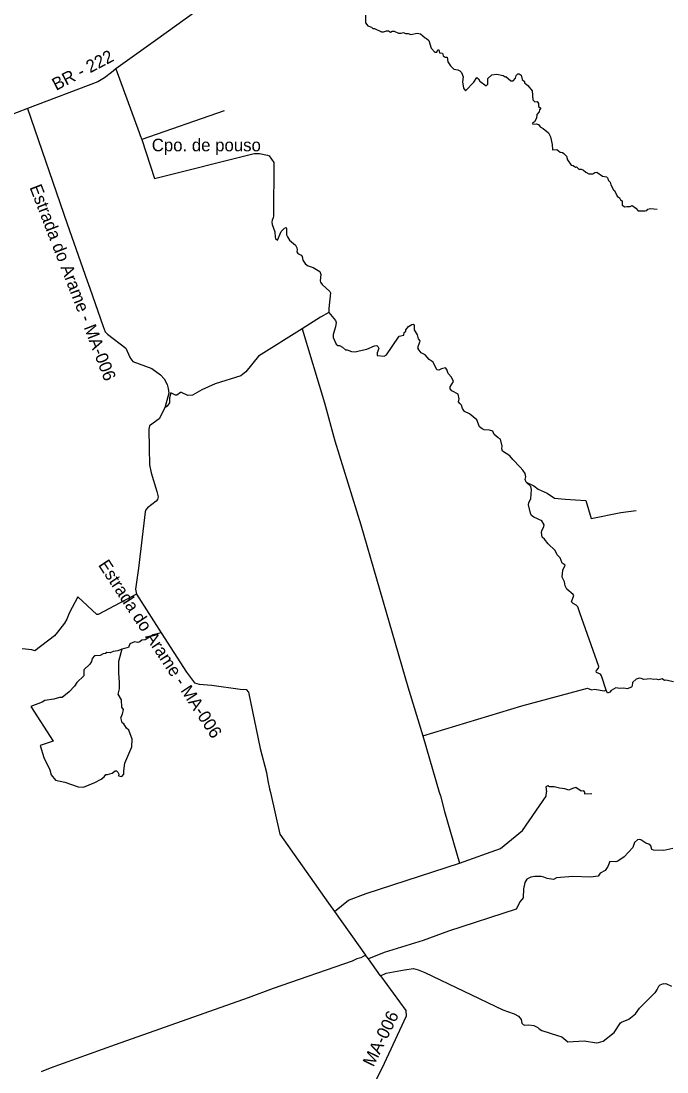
# Model space of a CAD drawing. Extents: x 332 to 501, y 9447 to 9559.
# Drawn here: x 359.78 to 379.35, y 9494.03 to 9525.86 of the extents above; entities that cross this region are included whole.
import ezdxf

# ---------------------------------------------------------------- set-up
doc = ezdxf.new("R2010")
doc.units = 0
for name, color, linetype in [('Level 1', 7, 'Continuous'), ('Level 13', 7, 'Continuous'), ('Level 2', 7, 'Continuous'), ('Level 31', 7, 'Continuous'), ('Level 5', 7, 'Continuous'), ('Level 6', 7, 'Continuous')]:
    doc.layers.add(name, color=color, linetype=linetype)

msp = doc.modelspace()

# ---------------------------------------------------------------- linework, layer by layer
at = {"layer": 'Level 1'}
msp.add_lwpolyline([(365.9301, 9523.1314), (363.4371, 9522.2704)], dxfattribs=at)
at = {"layer": 'Level 2'}
for points in [[(365.0749, 9526.1487), (363.8547, 9525.2686)], [(363.8547, 9525.2686), (362.6539, 9524.4042)], [(362.5174, 9524.3004), (362.304, 9524.1375), (362.1039, 9524.0174), (359.9733, 9523.2053)], [(362.6539, 9524.4042), (362.5174, 9524.3004)], [(359.9733, 9523.2053), (359.3502, 9522.9681), (356.5186, 9523.1911)], [(359.9733, 9523.2053), (361.1794, 9519.7092)], [(361.1794, 9519.7092), (361.7821, 9517.9924)], [(361.7821, 9517.9924), (361.8598, 9517.7681)], [(361.8598, 9517.7681), (362.2636, 9516.6001), (362.3311, 9516.447), (362.3941, 9516.375), (362.9521, 9515.9441), (363.0722, 9515.6726)], [(363.0722, 9515.6726), (363.0736, 9515.6676)], [(363.0736, 9515.6676), (363.1621, 9515.5469), (363.738, 9515.3308), (364.008, 9515.1372), (364.116, 9515.0201), (364.2015, 9514.8445), (364.2354, 9514.7302), (364.2534, 9514.5861), (364.1373, 9514.1464)], [(364.1373, 9514.1464), (363.9637, 9513.807), (363.672, 9513.5953), (363.6556, 9513.4916), (363.661, 9512.9157)], [(363.661, 9512.9157), (363.6725, 9512.4104), (363.7188, 9512.1731)], [(363.7188, 9512.1731), (363.896, 9511.6106), (363.9314, 9511.4469), (363.9124, 9511.3705), (363.8742, 9511.3187), (363.6097, 9511.1168), (363.5579, 9511.0568), (363.5416, 9510.9886), (363.3396, 9509.2835), (363.2469, 9508.6506), (363.2765, 9508.4962)], [(363.2765, 9508.4962), (364.0258, 9507.332)], [(364.0258, 9507.332), (364.79, 9506.1345), (365.0358, 9505.8141), (365.1787, 9505.7684), (365.5617, 9505.7398), (366.4193, 9505.6196), (366.5965, 9505.6139), (366.6651, 9505.5281), (367.0235, 9503.826), (367.2167, 9503.1019), (367.2567, 9502.8502)], [(367.2567, 9502.8502), (367.3073, 9502.6032)], [(367.3073, 9502.6032), (367.3315, 9502.4958)], [(367.3315, 9502.4958), (367.6153, 9501.2307), (369.0906, 9499.1393)], [(369.0906, 9499.1393), (369.2705, 9498.8886)], [(369.2705, 9498.8886), (370.2169, 9497.5702)], [(370.3034, 9497.4508), (370.2169, 9497.5702)], [(370.6661, 9496.9394), (370.3034, 9497.4508)], [(370.6661, 9496.9394), (371.4317, 9495.8895), (371.441, 9495.7173), (370.7059, 9494.1339), (369.2463, 9491.221), (368.7582, 9490.8961)]]:
    msp.add_lwpolyline(points, dxfattribs=at)
at = {"layer": 'Level 5'}
for points in [[(370.2183, 9526.0324), (370.2094, 9525.8015), (370.2849, 9525.7131), (370.3936, 9525.6665), (370.4353, 9525.6269), (370.4885, 9525.6269), (370.7032, 9525.5314), (370.7631, 9525.527), (370.8541, 9525.5581), (370.9074, 9525.5581), (370.9731, 9525.5226), (371.022, 9525.547), (371.0797, 9525.5448), (371.2106, 9525.4915), (371.2949, 9525.487), (371.3637, 9525.5048), (371.428, 9525.4826), (371.5101, 9525.4782), (371.5834, 9525.4493), (371.7808, 9525.4915), (371.8785, 9525.4715), (372.0177, 9525.3427), (372.065, 9525.3229)], [(372.065, 9525.3229), (372.1353, 9525.2693), (372.2075, 9525.0319), (372.3159, 9524.9132)], [(372.3159, 9524.9132), (372.3716, 9524.91), (372.4077, 9524.9823), (372.4335, 9524.9875), (372.4541, 9524.8894), (372.5419, 9524.879), (372.5625, 9524.8016), (372.6244, 9524.7655), (372.6863, 9524.7655), (372.7121, 9524.6157), (372.7895, 9524.497), (372.8927, 9524.3989), (373.0114, 9524.3782), (373.0682, 9524.3524), (373.1198, 9524.2956), (373.1714, 9524.1666), (373.1559, 9524.0117), (373.1869, 9523.8206), (373.2385, 9523.738), (373.4913, 9524.0013), (373.5893, 9524.1459), (373.6409, 9524.1098), (373.677, 9524.0323), (373.8731, 9523.8929), (373.9196, 9523.9394), (373.9196, 9524.1149), (374.0382, 9524.2234)], [(362.6539, 9524.4042), (363.3575, 9522.4841)], [(374.0382, 9524.2234), (374.1922, 9524.2459), (374.3852, 9524.2062), (374.442, 9524.1665), (374.4647, 9524.1721), (374.6123, 9524.0472), (374.6918, 9524.0472), (374.7599, 9524.121), (374.7826, 9524.2062), (374.828, 9524.2516), (374.8734, 9524.2573), (374.9302, 9524.2119), (374.9586, 9524.0813), (375.0324, 9524.0245), (375.0324, 9523.9791), (375.1289, 9523.9053), (375.2595, 9523.7407), (375.2878, 9523.4682), (375.3446, 9523.4115), (375.4184, 9523.4228), (375.4581, 9523.3604), (375.4581, 9523.2639), (375.5206, 9523.2128)], [(375.5206, 9523.2128), (375.4865, 9523.1674), (375.4752, 9523.1049), (375.4014, 9523.0254), (375.39, 9522.9176), (375.3332, 9522.804), (375.2765, 9522.7643)], [(375.2765, 9522.7643), (375.2822, 9522.7359), (375.3957, 9522.7416), (375.4581, 9522.7246), (375.5092, 9522.6565), (375.6001, 9522.6054), (375.7533, 9522.4748), (375.8214, 9522.3499), (375.8713, 9522.1197), (375.877, 9521.955)], [(363.3575, 9522.4841), (363.3928, 9522.3928)], [(363.3928, 9522.3928), (363.4371, 9522.2704)], [(363.4371, 9522.2704), (363.8235, 9521.0914)], [(375.877, 9521.955), (376.0076, 9521.9663), (376.1154, 9521.8811), (376.1835, 9521.8755), (376.2233, 9521.8471), (376.3027, 9521.7675), (376.3311, 9521.6539), (376.439, 9521.4892), (376.5071, 9521.4835), (376.5785, 9521.4298), (376.6069, 9521.4354), (376.6807, 9521.3673), (376.7488, 9521.3673), (376.8169, 9521.3389), (376.885, 9521.2764), (376.9758, 9521.231), (377.1007, 9521.2253), (377.1575, 9521.2707), (377.2199, 9521.2764), (377.3959, 9521.1571), (377.5151, 9521.1344), (377.5435, 9521.1117), (377.5719, 9521.0265), (377.623, 9520.9754), (377.6457, 9520.8958), (377.7252, 9520.7481), (377.7592, 9520.7197), (377.8387, 9520.555), (377.9068, 9520.4982), (377.9409, 9520.4357), (377.9863, 9520.413), (377.9863, 9520.3562)], [(363.8235, 9521.0914), (366.8443, 9521.8422), (367.0043, 9521.8472), (367.2496, 9521.7982), (367.2933, 9521.7736), (367.4323, 9521.5746), (367.4296, 9519.9548), (367.4187, 9519.892), (367.3832, 9519.8238), (367.3805, 9519.7638), (367.3859, 9519.6956), (367.465, 9519.4719), (367.4732, 9519.311), (367.4895, 9519.2701), (367.5441, 9519.2237), (367.6613, 9519.4774), (367.7567, 9519.5838), (367.8112, 9519.6002), (367.8249, 9519.562), (367.8249, 9519.3792), (367.8521, 9519.3219), (367.9094, 9519.221), (368.0967, 9519.0671), (368.1321, 9518.988), (368.143, 9518.9253), (368.1321, 9518.868), (368.1621, 9518.8162), (368.2603, 9518.7616), (368.293, 9518.7207), (368.3121, 9518.617), (368.3557, 9518.5516), (368.3993, 9518.497), (368.4756, 9518.4424), (368.6283, 9518.3961), (368.8293, 9518.2687), (368.862, 9518.1814), (368.8402, 9517.9877), (368.8538, 9517.9468), (368.9001, 9517.8813), (369.1319, 9517.6696), (369.1564, 9517.626), (369.0992, 9517.1541), (369.1046, 9517.0321)], [(377.9863, 9520.3562), (377.9863, 9520.2767), (378.0658, 9520.2256), (378.1282, 9520.2426), (378.2361, 9520.2369), (378.2928, 9520.2653), (378.4064, 9520.1858), (378.4745, 9520.1063), (378.6902, 9520.1063), (378.7356, 9520.1177), (378.7697, 9520.1574), (378.8491, 9520.1745), (379.0535, 9520.1631)], [(369.1046, 9517.0321), (369.3064, 9516.7866), (369.3254, 9516.7212), (369.3091, 9516.5989), (369.2382, 9516.3644)], [(368.2955, 9516.5359), (368.9764, 9514.2899), (369.29, 9513.1418), (370.0703, 9510.5959), (371.4932, 9505.6902), (371.9498, 9504.2075)], [(369.2382, 9516.3644), (369.2327, 9516.2689), (369.3227, 9516.0706), (369.3772, 9516.0324), (369.429, 9516.0269), (369.5179, 9515.9833), (369.6079, 9515.9014), (369.657, 9515.9014), (369.7933, 9515.8441), (369.8996, 9515.8332), (370.0187, 9515.872), (370.2532, 9515.9156), (370.4822, 9516.0165), (370.5558, 9516.0247), (370.5913, 9515.9974), (370.6131, 9515.9374), (370.5695, 9515.8065), (370.5695, 9515.7274), (370.7767, 9515.711), (370.8475, 9515.7438), (371.2115, 9516.2866), (371.2388, 9516.3139), (371.3723, 9516.3466), (371.3833, 9516.4202), (371.4378, 9516.4612), (371.4378, 9516.5075), (371.5196, 9516.603), (371.6177, 9516.6657), (371.6613, 9516.6767), (371.6859, 9516.6521), (371.6913, 9516.4993), (371.7813, 9516.3548), (371.814, 9516.2348), (371.8549, 9516.172), (371.8522, 9516.1256), (371.7922, 9515.9592)], [(371.7922, 9515.9592), (371.807, 9515.9303)], [(374.898, 9512.347), (374.675, 9512.574), (374.589, 9512.689), (374.366, 9512.829), (374.346, 9512.897), (374.355, 9512.981), (374.305, 9513.197), (374.229, 9513.236), (374.108, 9513.338), (374.068, 9513.44), (373.972, 9513.467), (373.809, 9513.476), (373.747, 9513.508), (373.667, 9513.569), (373.582, 9513.777), (373.369, 9513.956), (373.215, 9514.031), (373.157, 9514.121), (373.118, 9514.223), (373.07, 9514.268), (373.036, 9514.328), (373.054, 9514.418), (373.021, 9514.555), (372.826, 9514.656), (372.776, 9514.721), (372.782, 9514.773), (372.881, 9514.94), (372.816, 9515.075), (372.722, 9515.186), (372.678, 9515.305), (372.639, 9515.348), (372.595, 9515.346), (372.517, 9515.324), (372.439, 9515.28), (372.372, 9515.288), (372.261, 9515.523), (372.145, 9515.604), (372.017, 9515.742), (371.905, 9515.805), (371.807, 9515.9303)], [(376.7075, 9507.9315), (376.642, 9508.117), (376.599, 9508.163), (376.5, 9508.214), (376.451, 9508.267), (376.524, 9508.46), (376.508, 9508.489), (376.313, 9508.65), (376.267, 9508.754), (376.246, 9508.877), (376.175, 9509.012), (376.196, 9509.228), (376.261, 9509.374), (376.175, 9509.439), (376.111, 9509.594), (376.019, 9509.694), (375.955, 9509.818), (375.747, 9510.023), (375.638, 9510.165), (375.566, 9510.226), (375.548, 9510.362), (375.555, 9510.421), (375.62, 9510.545), (375.628, 9510.596), (375.558, 9510.716), (375.313, 9510.834), (375.246, 9510.884), (375.214, 9510.954), (375.153, 9511.199), (375.165, 9511.279), (375.227, 9511.387), (375.245, 9511.664), (375.218, 9511.76), (375.076, 9511.894), (375.055, 9511.974), (375.074, 9512.048), (375.046, 9512.149), (374.982, 9512.253), (374.898, 9512.347)], [(362.1128, 9507.8868), (362.0746, 9507.8868), (361.4966, 9508.4214), (361.2404, 9507.925), (361.1716, 9507.7417), (361.1008, 9507.6216), (360.8881, 9507.3434), (360.7954, 9507.2343), (360.1926, 9506.7832)], [(363.2765, 9508.4962), (362.1128, 9507.8868)], [(377.5049, 9505.5907), (377.364, 9506.024), (377.334, 9506.073), (377.215, 9506.124), (377.203, 9506.147), (377.209, 9506.191), (377.27, 9506.256), (377.279, 9506.307), (376.7075, 9507.9315)], [(364.0258, 9507.332), (363.7805, 9507.2636), (363.5347, 9507.115), (363.4432, 9507.1036), (363.3804, 9507.0578), (363.3175, 9507.0349), (363.2146, 9507.0578), (363.0774, 9506.9949), (363.0316, 9506.8863), (362.8316, 9506.8349)], [(360.1926, 9506.7832), (360.1029, 9506.8142), (359.8158, 9506.8415)], [(362.8316, 9506.8349), (362.7115, 9506.7777), (362.5743, 9506.7605), (362.4771, 9506.7262), (362.3799, 9506.732), (362.3399, 9506.7034), (362.2713, 9506.6919), (362.1741, 9506.6462), (362.0026, 9506.6348), (361.934, 9506.549), (361.9169, 9506.4576), (361.8654, 9506.3832), (361.6768, 9506.206), (361.6825, 9506.0231), (361.4664, 9505.8261), (361.3978, 9505.7174), (361.2377, 9505.5458), (361.0205, 9505.3742), (360.9462, 9505.3742), (360.769, 9505.3227), (360.5003, 9505.2827)], [(362.8316, 9506.8349), (362.7335, 9506.4559), (362.7277, 9506.1184), (362.7563, 9505.821), (362.7506, 9505.6322), (362.7106, 9505.4721), (362.8135, 9505.2947), (362.8249, 9505.0716), (362.8707, 9505.003), (362.8421, 9504.86), (362.8035, 9504.7601)], [(379.542, 9505.843), (379.311, 9505.891), (379.275, 9505.886), (379.203, 9505.934), (379.092, 9505.906), (379.019, 9505.921), (378.935, 9505.912), (378.846, 9505.934), (378.642, 9505.913), (378.563, 9505.946), (378.5, 9505.953), (378.417, 9505.927), (378.305, 9505.828), (378.292, 9505.72), (378.273, 9505.686), (378.145, 9505.632), (378.043, 9505.649), (377.919, 9505.639), (377.798, 9505.661), (377.654, 9505.58), (377.619, 9505.528), (377.5449, 9505.5049)], [(377.53, 9505.516), (377.5049, 9505.5907)], [(377.5449, 9505.5049), (377.53, 9505.516)], [(360.5003, 9505.2827), (360.4202, 9505.2312), (360.0772, 9505.0939), (360.7492, 9504.048)], [(360.8278, 9502.861), (361.108, 9502.8038), (361.5139, 9502.6608), (361.6682, 9502.6551), (362.0146, 9502.7981), (362.2033, 9502.8953), (362.3005, 9502.9697), (362.3519, 9503.0383), (362.4034, 9503.0383), (362.5406, 9503.0784), (362.6263, 9503.147), (362.6721, 9503.147), (362.7121, 9503.1127), (362.7407, 9503.044), (362.7349, 9502.9983), (362.8378, 9502.9811), (362.8893, 9503.0498), (362.8893, 9503.147), (362.9236, 9503.3758), (363.1351, 9503.8792), (363.1408, 9504.108), (363.0437, 9504.3768), (362.9693, 9504.4455), (362.8893, 9504.5713), (362.8436, 9504.5999), (362.8035, 9504.7601)], [(371.9498, 9504.2075), (372.4409, 9502.5041)], [(360.7492, 9504.048), (360.3574, 9503.9117), (360.4717, 9503.5531), (360.6489, 9503.1756), (360.6946, 9503.0269)], [(360.6946, 9503.0269), (360.8278, 9502.861)], [(372.4409, 9502.5041), (372.4853, 9502.3943), (372.6063, 9501.9168), (373.062, 9500.3565)], [(373.062, 9500.3565), (374.3056, 9500.7927), (374.9725, 9501.3446), (375.6839, 9502.3861), (375.7002, 9502.5091)], [(376.8496, 9502.5109), (376.8256, 9502.5394), (376.7491, 9502.5363), (376.5833, 9502.6415), (376.4877, 9502.616), (376.3761, 9502.5586), (376.2485, 9502.6064), (376.0859, 9502.6223), (375.9297, 9502.667), (375.7894, 9502.667), (375.7384, 9502.6893), (375.681, 9502.667), (375.7002, 9502.5091)], [(376.8496, 9502.5109), (376.8526, 9502.4534), (377.0701, 9502.4646)], [(379.5236, 9500.7951), (379.2487, 9500.7362), (378.9343, 9500.7463), (378.8923, 9500.7631), (378.8587, 9500.8724), (378.7965, 9500.9229), (378.7023, 9500.9548), (378.5594, 9501.054), (378.5258, 9501.0658), (378.4518, 9501.054), (378.3644, 9500.9783), (378.3139, 9500.8253), (378.0466, 9500.5395), (377.86, 9500.4133), (377.7995, 9500.3948), (377.6146, 9500.4032), (377.5557, 9500.2519), (377.475, 9500.1342), (377.3237, 9500.0451), (377.2632, 9499.9577), (377.0328, 9499.9291), (376.4915, 9499.9476), (376.0022, 9499.9107), (375.9122, 9499.8619), (375.7138, 9499.8854), (375.6196, 9499.9325), (375.5389, 9499.9527), (375.3439, 9499.9527), (375.2228, 9499.9258), (375.0984, 9499.8686), (375.0412, 9499.7677), (375.0043, 9499.5761), (374.9874, 9499.3037), (374.9, 9499.1893), (374.779, 9498.964), (372.7329, 9498.288), (371.9595, 9498.0056), (370.7825, 9497.6424), (370.3034, 9497.4508)], [(369.2705, 9498.8886), (369.7027, 9499.2329), (370.2363, 9499.4288), (373.062, 9500.3565)], [(370.2169, 9497.5702), (370.0742, 9497.4827), (369.9562, 9497.4575), (369.8129, 9497.3844), (367.4134, 9496.5527), (366.6604, 9496.2718), (362.6355, 9494.8479)], [(370.6661, 9496.9394), (370.839, 9497.0182), (371.3984, 9497.1245), (371.6703, 9497.162), (371.8098, 9497.1206)], [(371.8098, 9497.1206), (372.01, 9497.041), (374.3782, 9495.9143)], [(379.2346, 9496.6932), (379.1312, 9496.6598), (379.0853, 9496.6219), (379.0514, 9496.5321), (378.9773, 9496.4204)], [(379.2346, 9496.6932), (379.3147, 9496.7057)], [(379.3147, 9496.7057), (379.4784, 9496.6296)], [(377.9664, 9495.5348), (378.1865, 9495.63), (378.3896, 9495.7895), (378.5177, 9495.9585), (378.9773, 9496.4204)], [(374.3782, 9495.9143), (374.717, 9495.7857), (374.8451, 9495.72), (374.892, 9495.6668)], [(374.892, 9495.6668), (374.9321, 9495.6217), (374.9539, 9495.5028), (374.9852, 9495.4622), (375.0289, 9495.4465), (375.1602, 9495.4559), (375.3164, 9495.4309), (375.4383, 9495.3746), (375.4726, 9495.3385)], [(376.0345, 9495.138), (376.1637, 9495.0944), (376.3418, 9494.9412), (376.8418, 9494.9724), (377.2074, 9494.913), (377.2699, 9494.9161), (377.4106, 9494.9662), (377.7418, 9495.2258), (377.9387, 9495.5167), (377.9664, 9495.5348)], [(375.4726, 9495.3385), (375.556, 9495.284), (376.0345, 9495.138)], [(362.6355, 9494.8479), (360.6615, 9494.1476), (360.386, 9494.0296)]]:
    msp.add_lwpolyline(points, dxfattribs=at)
at = {"layer": 'Level 6'}
for points in [[(369.1046, 9517.0321), (368.85, 9516.8913), (368.2955, 9516.5359)], [(368.2955, 9516.5359), (366.9704, 9515.703), (366.5897, 9515.2321), (366.4425, 9515.1066), (365.6628, 9514.872), (365.2603, 9514.6849), (364.9713, 9514.5294), (364.8295, 9514.5158), (364.6371, 9514.609), (364.6098, 9514.609), (364.4953, 9514.5217), (364.4599, 9514.5217), (364.3181, 9514.6008), (364.2772, 9514.4398), (364.2718, 9514.298), (364.2066, 9514.1925), (364.1373, 9514.1464)], [(375.076, 9511.894), (375.3162, 9511.7803), (375.4463, 9511.6808), (375.7142, 9511.5583), (375.9361, 9511.4052), (376.2614, 9511.3746), (376.2614, 9511.3746), (376.8928, 9511.3325), (377.0497, 9510.791), (377.9452, 9510.9747), (378.4121, 9511.0283)], [(371.9498, 9504.2075), (374.9471, 9505.1125), (376.9376, 9505.6489), (377.0637, 9505.5984), (377.152, 9505.6173), (377.4457, 9505.574)], [(377.4457, 9505.574), (377.5049, 9505.5907)]]:
    msp.add_lwpolyline(points, dxfattribs=at)

# ---------------------------------------------------------------- texts
at = {"layer": 'Level 13'}
msp.add_text('Cpo. de pouso', height=0.38, dxfattribs=at).set_placement((363.7392, 9521.9105))
at = {"layer": 'Level 31'}
for s, rotation, p in [('BR - 222', 27.44903, (360.8436, 9523.7394)), ('Estrada do Arame - MA-006', 291.1597, (360.0316, 9520.8209)), ('Estrada do Arame - MA-006', 303.26522, (362.1032, 9509.3842)), ('MA-006', 63.96297, (370.454, 9494.1596))]:
    msp.add_text(s, height=0.38, rotation=rotation, dxfattribs=at).set_placement(p)

doc.saveas('drawing.dxf')
